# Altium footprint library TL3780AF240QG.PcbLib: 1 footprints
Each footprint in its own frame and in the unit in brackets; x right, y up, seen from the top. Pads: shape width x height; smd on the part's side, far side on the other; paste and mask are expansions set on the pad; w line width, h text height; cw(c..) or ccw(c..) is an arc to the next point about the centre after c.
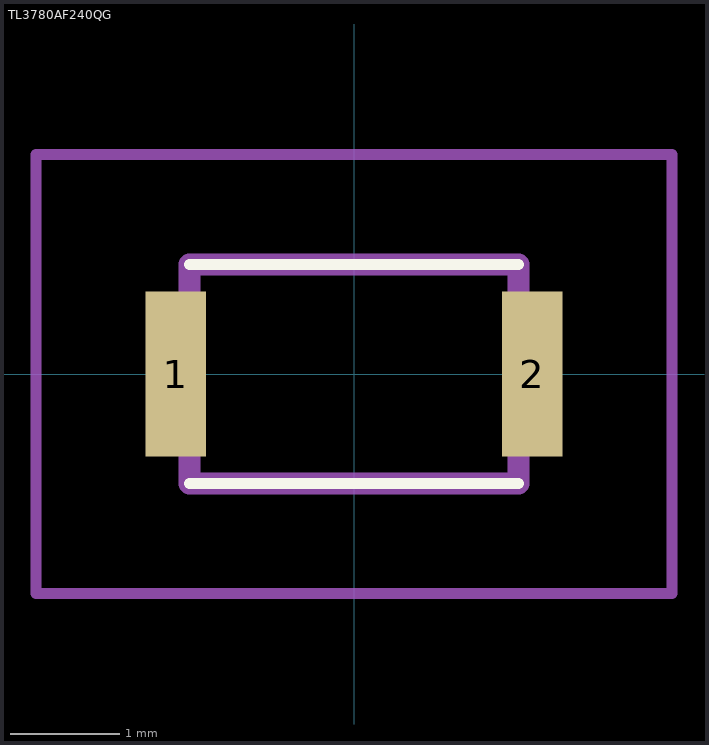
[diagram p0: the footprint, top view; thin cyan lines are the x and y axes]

## TL3780AF240QG [mm]
pads (2):
  rect 0.55x1.5 smd: 1(-1.625,0) 2(1.625,0)
Top Overlay:
  lines w0.1: -1.5,-1 1.5,-1 ; -1.5,1 1.5,1
Mechanical 15:
  lines w0.2: -1.5,-1 1.5,-1 1.5,1 -1.5,1 -1.5,-1
Mechanical 20:
  lines w0.1: -2.9,-2 2.9,-2 2.9,2 -2.9,2 -2.9,-2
